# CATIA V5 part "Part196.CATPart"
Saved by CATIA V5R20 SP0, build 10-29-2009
Part number: IA 8717SF
Revision: ANY
Definition: UNKNOWN
Nomenclature: IA 8717SF
Source: Unknown
Bounding box of the stored display mesh (mm): x -4.35 to 4.35, y -17 to 0, z -4.35 to 4.35
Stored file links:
  C:\Users\Utente\Desktop\IO LAVORO\3D X SITO CF\CUMSA\3D files FA\FA 168710-20\Part196.CATPart
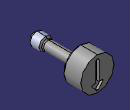
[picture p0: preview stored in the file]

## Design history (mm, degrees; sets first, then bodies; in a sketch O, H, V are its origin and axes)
Body1 "Cortar-Extruir1" (main body)
  Solid1: solid without history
